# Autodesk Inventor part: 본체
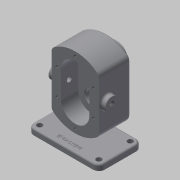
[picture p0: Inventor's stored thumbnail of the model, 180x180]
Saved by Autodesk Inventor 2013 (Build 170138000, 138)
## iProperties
Created: 2019-03
Part Number: 본체
Material: Generic
Document SubType Name: Modeling
Designer: Administrator
Density: 1 g/cm^3
Author: Administrator
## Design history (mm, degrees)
sketch "스케치5"
  geometry: L1 (-40, 44.721)-(40, 44.721); L2 (40, 44.721)-(40, -44.721); L3 (40, -44.721)-(-40, -44.721); L4 (-40, -44.721)-(-40, 44.721); A1 r 60 centre (0, 0) between (40, 44.721) and (-40, 44.721); A2 r 60 centre (0, 0) between (-40, -44.721) and (40, -44.721); 3 further points
  constraints: 8 end point, 4 point on circle, 2 centre point, 2 coincident, 2 midpoint, 2 parallel, 1 horizontal, 1 perpendicular, 1 vertical alignment
  dimensions: "d17" = 80 distance of L2.end L3.end; "d20" = 60 radius of A1; "d21" = 60 radius of A2
extrude "돌출2" new body sketch "스케치5" distance "d22" = 53; taper "d23" = 0 deg
sketch "스케치7"
  geometry: L1 (-24, 22)-(-24, -22); L2 (24, 22)-(24, -22); A1 r 60 centre (0, 0) between (40, 44.721) and (-40, 44.721) reference; A2 r 24 centre (0, -22) between (-24, -22) and (24, -22); A3 r 24 centre (0, 22) between (24, 22) and (-24, 22)
  constraints: 4 end point, 4 point on circle, 4 tangent, 2 centre point, 2 vertical alignment
  dimensions: "d25" = 24 radius of A2; "d26" = 22 distance of A1.centre A3.centre; "d27" = 44 distance of A2.centre A3.centre; "d28" = 24 radius of A3
extrude "돌출3" cut sketch "스케치7" distance "d29" = 29; taper "d30" = 0 deg
sketch "스케치8"
  geometry: C1 r 12.5 at (0, 22); C2 r 12.5 at (0, -22); A1 r 24 centre (0, -22) between (-24, -22) and (24, -22) reference; A2 r 24 centre (0, 22) between (24, 22) and (-24, 22) reference; 1 further point
  constraints: 2 centre point, 2 coincident
  dimensions: "d31" = 25 diameter of C1; "d32" = 25 diameter of C2
extrude "돌출4" cut sketch "스케치8" distance "d33" = 15; taper "d34" = 0 deg
sketch "스케치9"
  geometry: C1 r 12.5 at (0, 22) reference; C2 r 12.5 at (0, -22) reference; C3 r 19 at (0, 22)
  constraints: 1 centre point, 1 coincident
  dimensions: "d35" = 38 diameter of C3
extrude "돌출5" join sketch "스케치9" distance "d36" = 17; taper "d37" = 0 deg
sketch "스케치10"
  geometry: C1 r 19 at (0, 0) reference; C2 r 14 at (0, 0); 1 further point
  constraints: 1 centre point, 1 coincident
  dimensions: "d38" = 28 diameter of C2
extrude "돌출6" cut sketch "스케치10" distance "d39" = 7.3; taper "d40" = 0 deg
sketch "스케치11"
  geometry: C1 r 12.5 at (0, 0) reference; C2 r 8.5 at (0, 0); 1 further point
  constraints: 1 centre point, 1 coincident
  dimensions: "d41" = 17 diameter of C2
hole "구멍2" sketch "스케치11" at (0, 0) diameter "d42" = 17; stored, may be unused: countersink angle "d46" = 90 deg, drill point angle "d48" = 118 deg; dims "d43" = 6, "d44" = 4, "d45" = 2, "d47" = 8
node "작업 평면2"
sketch "스케치12"
  geometry: L1 (60, 73)-(-60, 73); L2 (-60, 73)-(-60, 0); L3 (-60, 0)-(60, 0); L4 (60, 0)-(60, 73); L5 (40, 0)-(-40, 0) reference; 3 further points
  constraints: 8 end point, 2 midpoint, 2 parallel, 1 coincident, 1 horizontal, 1 perpendicular
  dimensions: "d50" = 73 distance of L3.end L1.start; "d52" = 120 distance of L1.start L1.end
extrude "돌출7" join sketch "스케치12" distance "d53" = 10; taper "d54" = 0 deg
fillet "모깎기3" dims "d55" = 10
sketch "스케치13"
  geometry: A1 r 10 centre (-50, -63) between (-60, -63) and (-50, -73) reference; A2 r 10 centre (50, -63) between (50, -73) and (60, -63) reference; A3 r 10 centre (50, -10) between (60, -10) and (50, 0) reference; A4 r 10 centre (-50, -10) between (-50, 0) and (-60, -10) reference; 1 further point
hole "구멍3" sketch "스케치13" at (50, -10), (50, -63), (-50, -10), (-50, -63) diameter "d56" = 9; stored, may be unused: countersink angle "d60" = 90 deg, drill point angle "d62" = 118 deg; dims "d57" = 6, "d58" = 4, "d59" = 2, "d61" = 8
sketch "스케치15"
  geometry: L1 (-6, 0)-(6, 0); L2 (6, 0)-(6, -43); L3 (6, -43)-(-6, -43); L4 (-6, -43)-(-6, 0); 2 further points
  constraints: 8 end point, 2 parallel, 1 coincident, 1 horizontal, 1 midpoint, 1 perpendicular
  dimensions: "d64" = 12 distance of L2.end L3.end; "d65" = 43 distance of L1.end L2.end
extrude "돌출8" join sketch "스케치15" stored distance "d66" = 10; taper "d67" = 0 deg
fillet "모깎기5" dims "d68" = 3
sketch "스케치16"
  geometry: L1 (0, 89.443)-(-53, 89.443) reference; L2 (-63, -33.279)-(-10, -33.279) reference; L3 (-53, 0)-(-53, 89.443) reference; C1 r 11 at (-39, 44.721); 2 further points
  constraints: 1 centre point, 1 midpoint
  dimensions: "d69" = 22 diameter of C1; "d70" = 78 distance from line of L2 C1.centre; "d73" = 14 distance from line of L3 C1.centre
extrude "돌출9" join sketch "스케치16" distance "d71" = 8; taper "d72" = 0 deg
sketch "스케치19"
  geometry: C1 r 11 at (0, 0) reference; 1 further point
hole "구멍4" sketch "스케치19" at (0, 0) diameter "d74" = 8.376; stored, may be unused: countersink angle "d78" = 90 deg, drill point angle "d80" = 118 deg; dims "d75" = 10, "d76" = 4, "d77" = 2, "d79" = 8
sketch "스케치20"
  geometry: L1 (-31, -22)-(-31, 22); L2 (31, 22)-(31, -22); A1 r 24 centre (0, -22) between (-24, -22) and (24, -22) reference; A2 r 24 centre (0, 22) between (24, 22) and (-24, 22) reference; A3 r 31 centre (0, 22) between (31, 22) and (-31, 22); A4 r 31 centre (0, -22) between (-31, -22) and (31, -22); 8 further points
  constraints: 8 coincident, 6 point on circle, 4 end point, 4 tangent, 2 centre point
  dimensions: "d84" = 31 radius of A3; "d86" = 31 radius of A4
hole "구멍5" sketch "스케치20" diameter "d87" = 4.134; stored, may be unused: countersink angle "d91" = 90 deg, drill point angle "d93" = 118 deg; dims "d88" = 10, "d89" = 4, "d90" = 2, "d92" = 12
hole "구멍6" sketch "스케치20" diameter "d94" = 4.134; stored, may be unused: countersink angle "d98" = 90 deg, drill point angle "d100" = 118 deg; dims "d95" = 10, "d96" = 4, "d97" = 2, "d99" = 12
chamfer "모따기1" distance "d101" = 0.7; stored, may be unused: second distance "d102" = 2, angle "d103" = 30 deg
sketch "스케치21"
  geometry: L1 (-27.63, -55.961)-(27.63, -55.961); L2 (27.63, -55.961)-(27.63, -68.726); L3 (27.63, -68.726)-(-27.63, -68.726); L4 (-27.63, -68.726)-(-27.63, -55.961); L5 (-50, -73)-(50, -73) reference; 3 further points
  constraints: 2 midpoint, 1 vertical alignment, 2 other
  dimensions: "d104" = 12.7654 distance of L1.end L2.end
feature "엠보싱1" sketch "스케치21" dims "d17" = 80, "d20" = 60, "d21" = 60, "d107" = 0.5, "d108" = 0
fillet "모깎기6" dims "d109" = 10
fillet "모깎기7" dims "d110" = 3
chamfer "모따기2" distance "d111" = 1; stored, may be unused: second distance "d112" = 2, angle "d113" = 30 deg
fillet "모깎기8" dims "d114" = 3
fillet "모깎기9" dims "d115" = 0.5
node "솔리드2"
mirror "대칭1"
mirror "대칭2"
other parameters: "d24" = 24, "d49" = -78, "d81" = 31, "d83" = 31
